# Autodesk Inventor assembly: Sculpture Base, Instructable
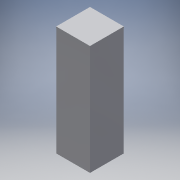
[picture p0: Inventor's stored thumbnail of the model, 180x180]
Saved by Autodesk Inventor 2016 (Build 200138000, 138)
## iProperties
Created: 2015-08
Part Number: Sculpture Base, Instructable
Document SubType Name: Assembly
Designer: Chris Eckert
Author: Chris Eckert
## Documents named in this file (4)
- C:\Users\Chris Eckert\Documents\My Art CAD\Look\Installation\Sculpture Base\Instructables\Sculpture Base, Instructable.iam
- C:\Users\Chris Eckert\Documents\My Art CAD\Look\Installation\Sculpture Base\Sculpture Base, Front & Back.ipt
- C:\Users\Chris Eckert\Documents\My Art CAD\Look\Installation\Sculpture Base\Sculpture Base, Sides.ipt
- C:\Users\Chris Eckert\Documents\My Art CAD\Look\Installation\Sculpture Base\Sculpture Base, Top.ipt
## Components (5 placed, 3 different names)
1. Sculpture Base, Front & Back:1 — Mate:1, Flush:1, Mate:2, Mate:3, Flush:2, Mate:4, Mate:7, Flush:4, Flush:5
2. Sculpture Base, Front & Back:2 — Mate:5, Flush:3, Mate:6
3. Sculpture Base, Sides:1 — Mate:3, Flush:2, Mate:4, Mate:5, Flush:3, Mate:6
4. Sculpture Base, Sides:2 — Mate:1, Flush:1, Mate:2
5. Sculpture Base, Top:1 — Mate:7, Flush:4, Flush:5
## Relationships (12: Mate 7, Flush 5)
- Mate:1: Sculpture Base, Front & Back:1 ↔ Sculpture Base, Sides:2
- Flush:1: Sculpture Base, Front & Back:1 ↔ Sculpture Base, Sides:2
- Mate:2: Sculpture Base, Front & Back:1 ↔ Sculpture Base, Sides:2
- Mate:3: Sculpture Base, Front & Back:1 ↔ Sculpture Base, Sides:1
- Flush:2: Sculpture Base, Front & Back:1 ↔ Sculpture Base, Sides:1
- Mate:4: Sculpture Base, Front & Back:1 ↔ Sculpture Base, Sides:1
- Mate:5: Sculpture Base, Front & Back:2 ↔ Sculpture Base, Sides:1
- Flush:3: Sculpture Base, Front & Back:2 ↔ Sculpture Base, Sides:1
- Mate:6: Sculpture Base, Front & Back:2 ↔ Sculpture Base, Sides:1
- Mate:7: Sculpture Base, Front & Back:1 ↔ Sculpture Base, Top:1
- Flush:4: Sculpture Base, Front & Back:1 ↔ Sculpture Base, Top:1
- Flush:5: Sculpture Base, Front & Back:1 ↔ Sculpture Base, Top:1
## Named parameters: WoodThickness = 12.7 mm, OverallHeight = 1193.8 mm, OverallWidth = 368.3 mm, OverallDepth = 368.3 mm, DatoOverhang = 1.5875 mm
